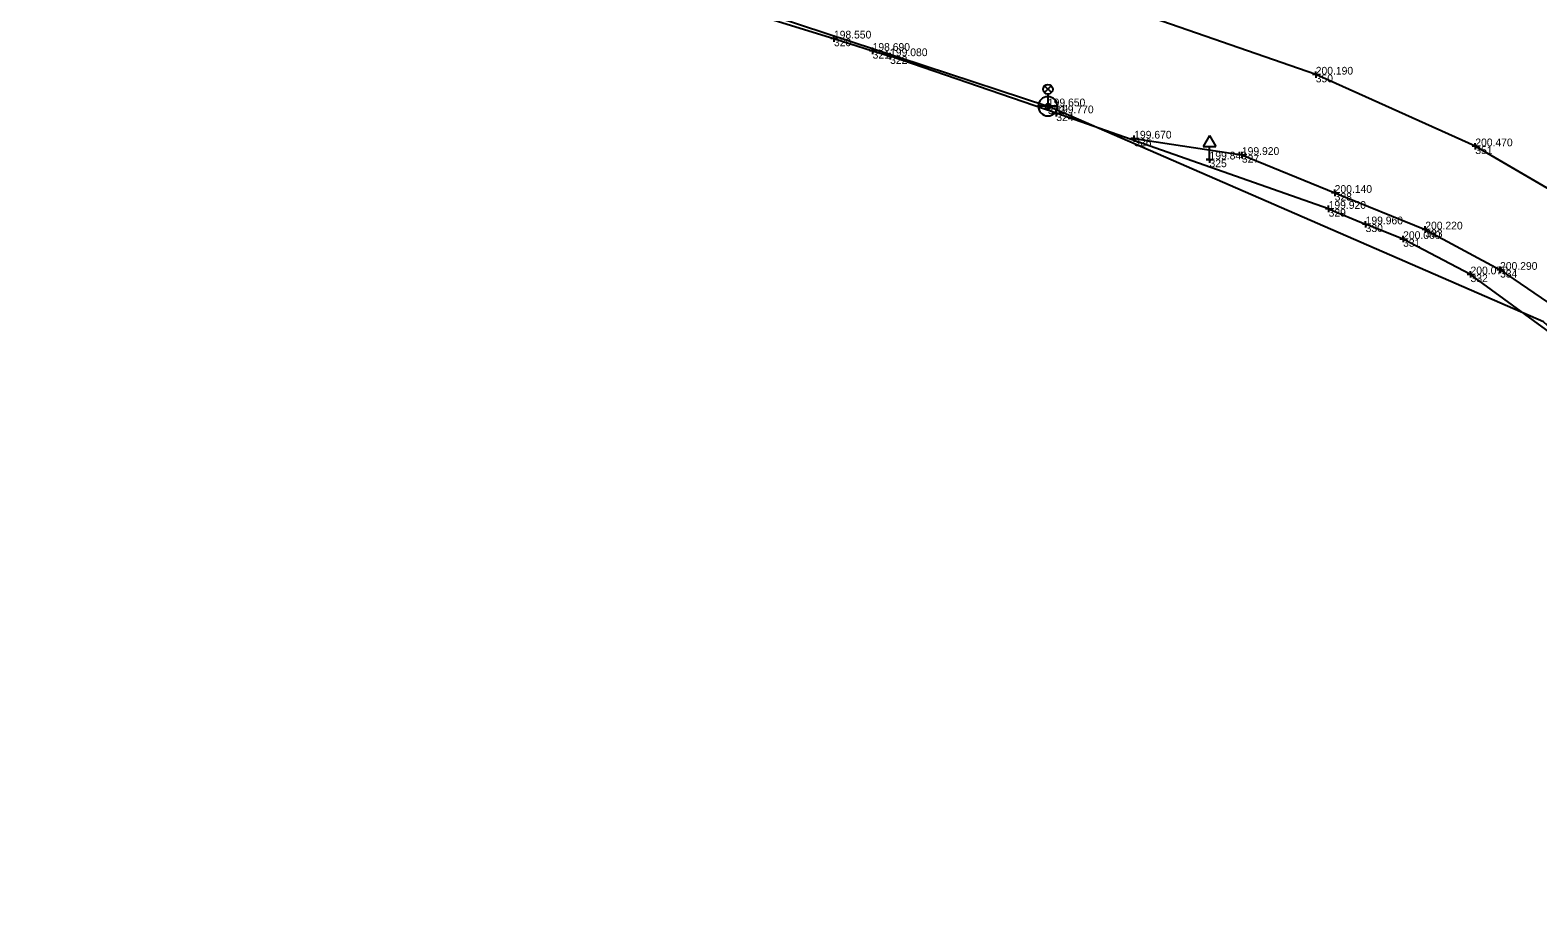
# Model space of a CAD drawing. Extents: x -744883 to -744469, y -966832 to -966374.
# Drawn here: x -744784.8 to -744667.9, y -966696.8 to -966629.2 of the extents above; entities that cross this region are included whole.
import ezdxf

# ---------------------------------------------------------------- set-up
doc = ezdxf.new("R2010")
doc.units = 0
for name, color, linetype in [('Body polohopisu', 7, 'Continuous'), ('Doplňkové značky', 7, 'Continuous'), ('Ploty_opěrné zdi', 7, 'Continuous'), ('Rozhraní ploch', 7, 'Continuous'), ('Vrstva 132', 7, 'Continuous'), ('Vstup na pozemek', 7, 'Continuous'), ('Výšky bodů', 7, 'Continuous'), ('Značky IS', 7, 'Continuous'), ('Čísla bodů', 7, 'Continuous')]:
    doc.layers.add(name, color=color, linetype=linetype)

msp = doc.modelspace()

# ---------------------------------------------------------------- linework, layer by layer
at = {"layer": 'Body polohopisu'}
for p, q in [((-744722.49, -966629.87), (-744722.74, -966629.87)), ((-744722.49, -966629.87), (-744722.49, -966629.62)), ((-744722.49, -966629.87), (-744722.24, -966629.87)), ((-744722.49, -966629.87), (-744722.49, -966630.12)), ((-744719.49, -966630.83), (-744719.74, -966630.83)), ((-744719.49, -966630.83), (-744719.49, -966630.58)), ((-744719.49, -966630.83), (-744719.24, -966630.83)), ((-744719.49, -966630.83), (-744719.49, -966631.08)), ((-744718.13, -966631.24), (-744718.38, -966631.24)), ((-744718.13, -966631.24), (-744718.13, -966630.99)), ((-744718.13, -966631.24), (-744717.88, -966631.24)), ((-744718.13, -966631.24), (-744718.13, -966631.49)), ((-744685.11, -966632.67), (-744685.36, -966632.67)), ((-744685.11, -966632.67), (-744685.11, -966632.42)), ((-744685.11, -966632.67), (-744684.86, -966632.67)), ((-744685.11, -966632.67), (-744685.11, -966632.92)), ((-744705.89, -966635.13), (-744706.14, -966635.13)), ((-744705.89, -966635.13), (-744705.89, -966634.88)), ((-744705.89, -966635.13), (-744705.64, -966635.13)), ((-744705.89, -966635.13), (-744705.89, -966635.38)), ((-744705.24, -966635.67), (-744705.49, -966635.67)), ((-744705.24, -966635.67), (-744705.24, -966635.42)), ((-744705.24, -966635.67), (-744704.99, -966635.67)), ((-744705.24, -966635.67), (-744705.24, -966635.92)), ((-744699.195, -966637.631), (-744699.195, -966637.381)), ((-744699.195, -966637.631), (-744699.445, -966637.631)), ((-744699.195, -966637.631), (-744698.945, -966637.631)), ((-744699.195, -966637.631), (-744699.195, -966637.881)), ((-744690.84, -966638.9), (-744690.84, -966638.65)), ((-744672.73, -966638.23), (-744672.98, -966638.23)), ((-744672.73, -966638.23), (-744672.73, -966637.98)), ((-744672.73, -966638.23), (-744672.48, -966638.23)), ((-744672.73, -966638.23), (-744672.73, -966638.48)), ((-744693.35, -966639.25), (-744693.6, -966639.25)), ((-744693.35, -966639.25), (-744693.35, -966639)), ((-744693.35, -966639.25), (-744693.1, -966639.25)), ((-744693.35, -966639.25), (-744693.35, -966639.5)), ((-744690.84, -966638.9), (-744691.09, -966638.9)), ((-744690.84, -966638.9), (-744690.59, -966638.9)), ((-744690.84, -966638.9), (-744690.84, -966639.15)), ((-744683.64, -966641.84), (-744683.89, -966641.84)), ((-744683.64, -966641.84), (-744683.64, -966641.59)), ((-744683.64, -966641.84), (-744683.39, -966641.84)), ((-744683.64, -966641.84), (-744683.64, -966642.09)), ((-744684.11, -966643.08), (-744684.36, -966643.08)), ((-744684.11, -966643.08), (-744684.11, -966642.83)), ((-744684.11, -966643.08), (-744683.86, -966643.08)), ((-744684.11, -966643.08), (-744684.11, -966643.33)), ((-744681.24, -966644.28), (-744681.49, -966644.28)), ((-744681.24, -966644.28), (-744681.24, -966644.03)), ((-744681.24, -966644.28), (-744680.99, -966644.28)), ((-744681.24, -966644.28), (-744681.24, -966644.53)), ((-744676.61, -966644.68), (-744676.61, -966644.43)), ((-744678.33, -966645.42), (-744678.58, -966645.42)), ((-744678.33, -966645.42), (-744678.33, -966645.17)), ((-744678.33, -966645.42), (-744678.08, -966645.42)), ((-744678.33, -966645.42), (-744678.33, -966645.67)), ((-744676.61, -966644.68), (-744676.86, -966644.68)), ((-744676.61, -966644.68), (-744676.36, -966644.68)), ((-744676.61, -966644.68), (-744676.61, -966644.93)), ((-744673.1, -966648.16), (-744673.1, -966647.91)), ((-744670.81, -966647.81), (-744671.06, -966647.81)), ((-744670.81, -966647.81), (-744670.81, -966647.56)), ((-744670.81, -966647.81), (-744670.56, -966647.81)), ((-744670.81, -966647.81), (-744670.81, -966648.06)), ((-744673.1, -966648.16), (-744673.35, -966648.16)), ((-744673.1, -966648.16), (-744672.85, -966648.16)), ((-744673.1, -966648.16), (-744673.1, -966648.41))]:
    msp.add_line(p, q, dxfattribs=at)
at = {"layer": 'Doplňkové značky'}
for p, q in [((-744706.154, -966634.068), (-744705.626, -966633.54)), ((-744705.618, -966634.065), (-744706.146, -966633.536)), ((-744705.89, -966634.18), (-744705.89, -966634.93)), ((-744693.35, -966637.384), (-744693.85, -966638.25)), ((-744693.35, -966637.384), (-744692.85, -966638.25)), ((-744693.85, -966638.25), (-744692.85, -966638.25)), ((-744693.35, -966639.25), (-744693.35, -966638.25)), ((-744693.6, -966639.25), (-744693.1, -966639.25))]:
    msp.add_line(p, q, dxfattribs=at)
for centre, radius in [((-744705.89, -966633.805), 0.375), ((-744705.89, -966635.13), 0.2)]:
    msp.add_circle(centre, radius, dxfattribs=at)
at = {"layer": 'Ploty_opěrné zdi'}
for points in [[(-744734.44, -966626.17), (-744722.49, -966629.87)], [(-744684.11, -966643.08), (-744705.24, -966635.67), (-744718.13, -966631.24)], [(-744665.64, -966653.62), (-744673.1, -966648.16), (-744678.33, -966645.42), (-744681.24, -966644.28)]]:
    msp.add_lwpolyline(points, dxfattribs=at)
at = {"layer": 'Rozhraní ploch'}
for points in [[(-744656.07, -966650.16), (-744662.8, -966644.01), (-744672.73, -966638.23), (-744685.11, -966632.67), (-744699.67, -966627.63), (-744718.38, -966621.41), (-744745.96, -966612.84), (-744758.4, -966608.84), (-744770.58, -966603.83), (-744782.97, -966596.56), (-744784.85, -966594.86)], [(-744699.195, -966637.631), (-744690.84, -966638.9), (-744683.64, -966641.84), (-744676.61, -966644.68), (-744670.81, -966647.81), (-744662.9, -966653.21)]]:
    msp.add_lwpolyline(points, dxfattribs=at)
at = {"layer": 'Vrstva 132'}
for points in [[(-744784.17, -966607.48), (-744744.28, -966622.47), (-744705.89, -966635.13)], [(-744622.6, -966696.82), (-744637.75, -966679.16), (-744667.44, -966651.83), (-744705.89, -966635.13)]]:
    msp.add_lwpolyline(points, dxfattribs=at)
at = {"layer": 'Vstup na pozemek'}
for points in [[(-744722.49, -966629.87), (-744719.49, -966630.83), (-744718.13, -966631.24)], [(-744684.11, -966643.08), (-744681.24, -966644.28)]]:
    msp.add_lwpolyline(points, dxfattribs=at)
at = {"layer": 'Značky IS'}
msp.add_line((-744705.142, -966635.13), (-744706.638, -966635.13), dxfattribs=at)
for start, end in [(0, 180), (180, 0)]:
    msp.add_arc((-744705.89, -966635.13), 0.747, start, end, dxfattribs=at)

# ---------------------------------------------------------------- texts
at = {"layer": 'Výšky bodů'}
for s, p in [('198.550', (-744722.49, -966629.87)), ('198.690', (-744719.49, -966630.83)), ('199.080', (-744718.13, -966631.24)), ('200.190', (-744685.11, -966632.67)), ('199.650', (-744705.89, -966635.13)), ('199.770', (-744705.24, -966635.67)), ('199.670', (-744699.195, -966637.631)), ('199.840', (-744693.35, -966639.25)), ('199.920', (-744690.84, -966638.9)), ('200.470', (-744672.73, -966638.23)), ('200.140', (-744683.64, -966641.84)), ('199.920', (-744684.11, -966643.08)), ('199.960', (-744681.24, -966644.28)), ('200.220', (-744676.61, -966644.68)), ('200.060', (-744678.33, -966645.42)), ('200.070', (-744673.1, -966648.16)), ('200.290', (-744670.81, -966647.81))]:
    msp.add_text(s, height=0.6, dxfattribs=at).set_placement(p)
at = {"layer": 'Čísla bodů'}
for s, p in [('320', (-744722.49, -966630.47)), ('321', (-744719.49, -966631.43)), ('322', (-744718.13, -966631.84)), ('350', (-744685.11, -966633.27)), ('323', (-744705.89, -966635.73)), ('324', (-744705.24, -966636.27)), ('326', (-744699.195, -966638.231)), ('351', (-744672.73, -966638.83)), ('325', (-744693.35, -966639.85)), ('327', (-744690.84, -966639.5)), ('328', (-744683.64, -966642.44)), ('329', (-744684.11, -966643.68)), ('330', (-744681.24, -966644.88)), ('331', (-744678.33, -966646.02)), ('333', (-744676.61, -966645.28)), ('334', (-744670.81, -966648.41)), ('332', (-744673.1, -966648.76))]:
    msp.add_text(s, height=0.6, dxfattribs=at).set_placement(p)

doc.saveas('drawing.dxf')
